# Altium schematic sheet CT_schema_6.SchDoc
size 582 x 363 mm
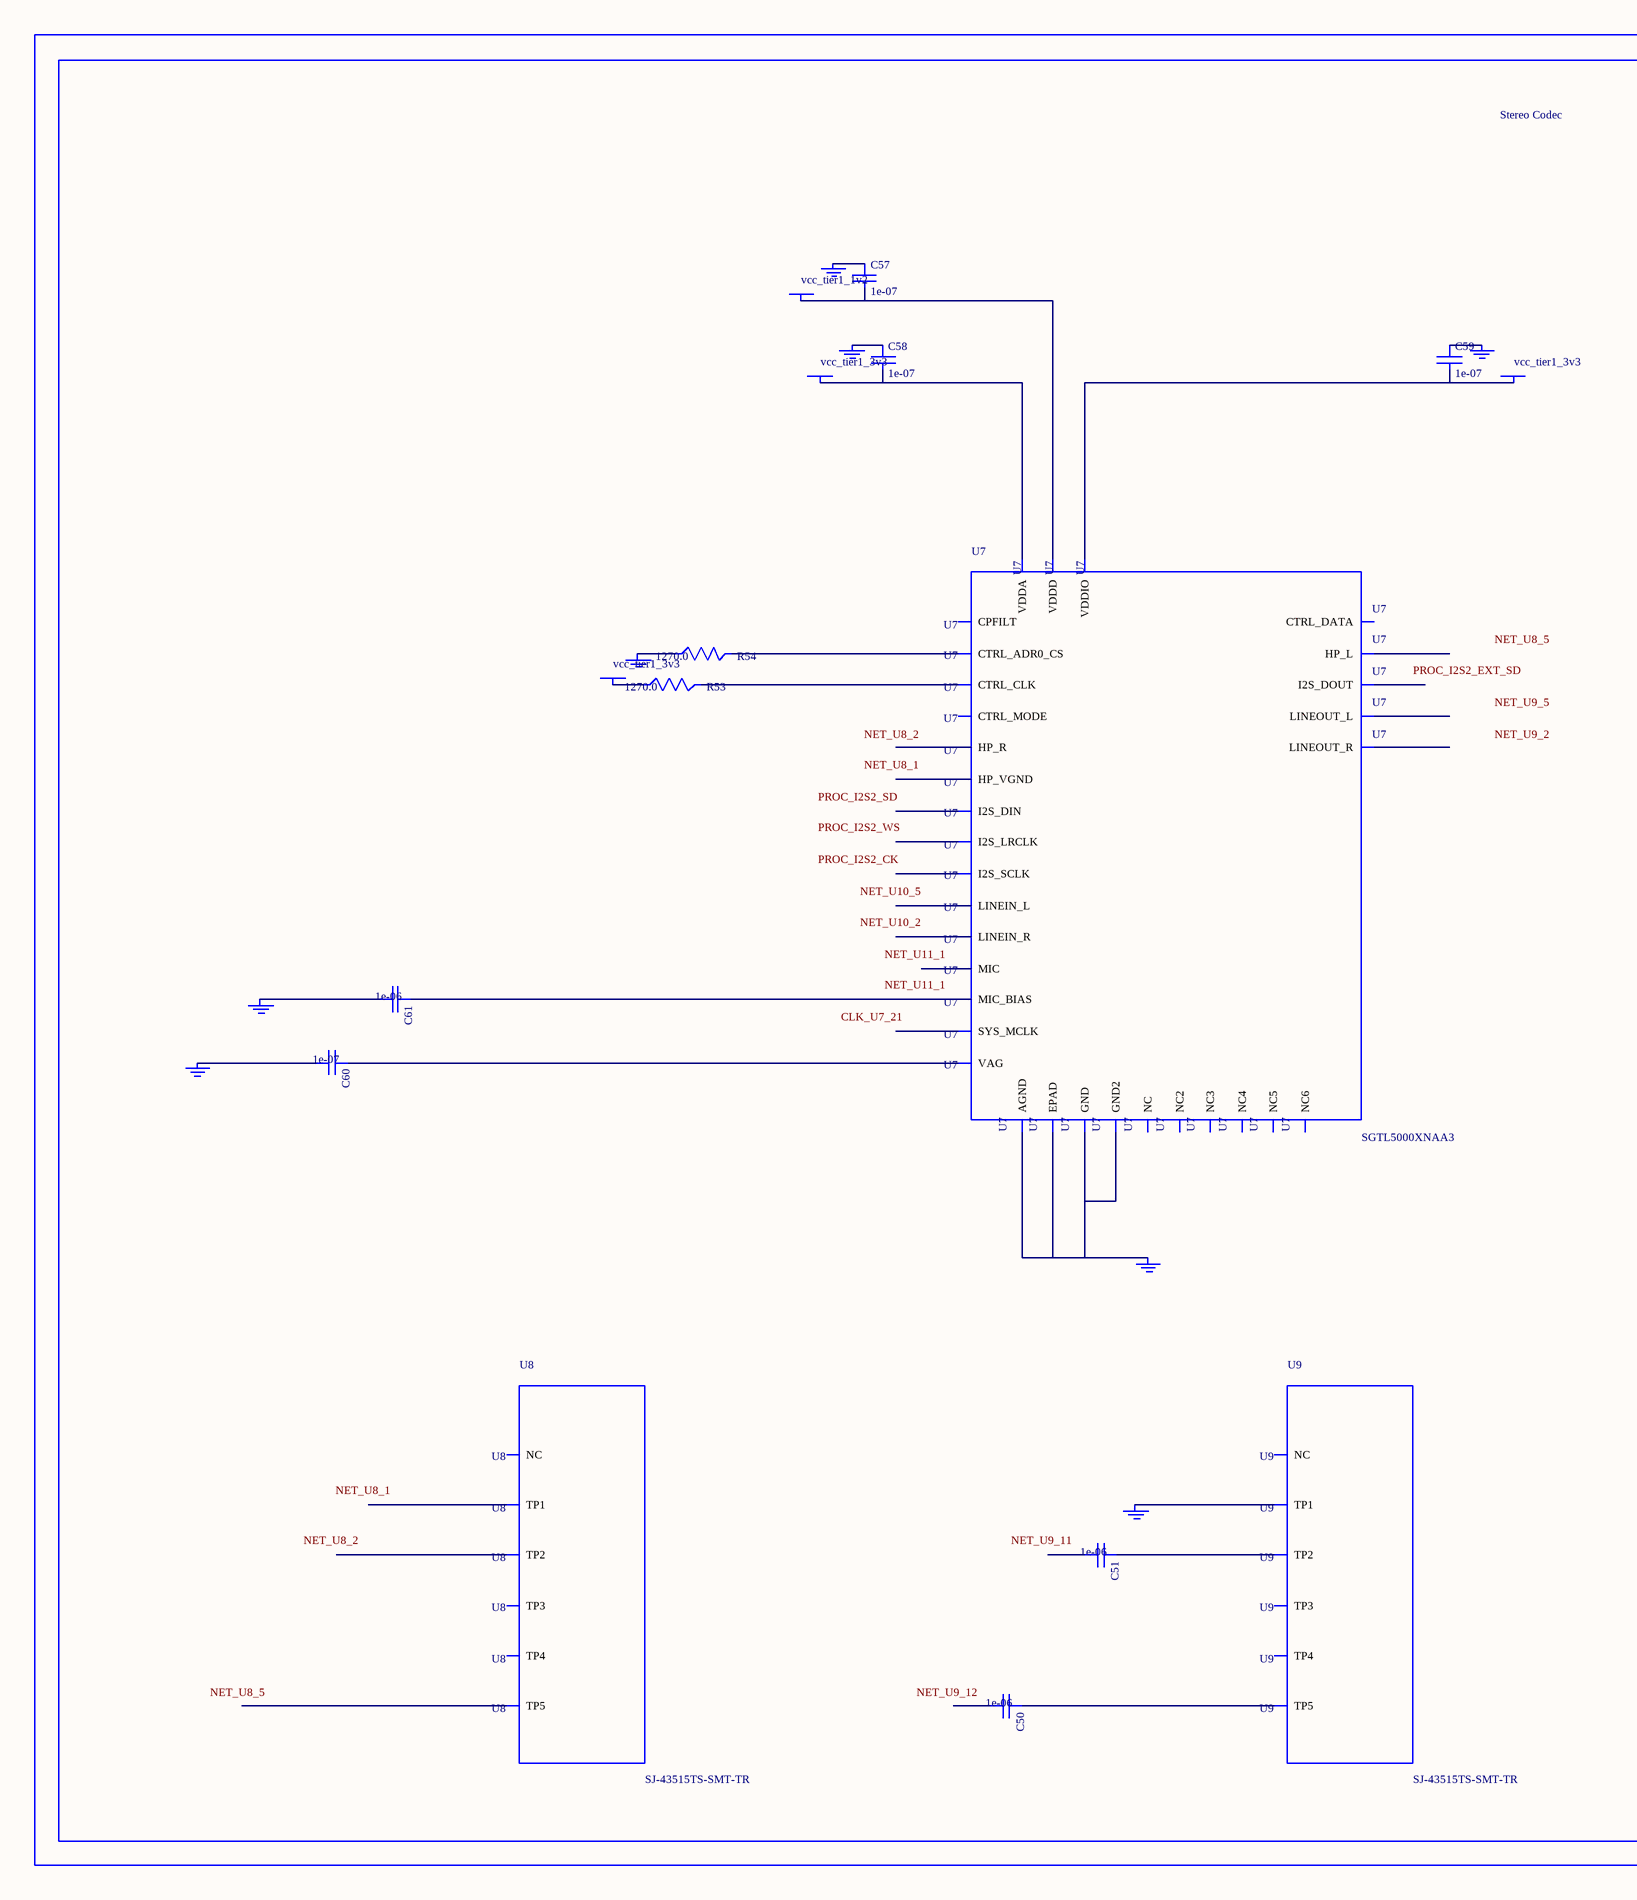
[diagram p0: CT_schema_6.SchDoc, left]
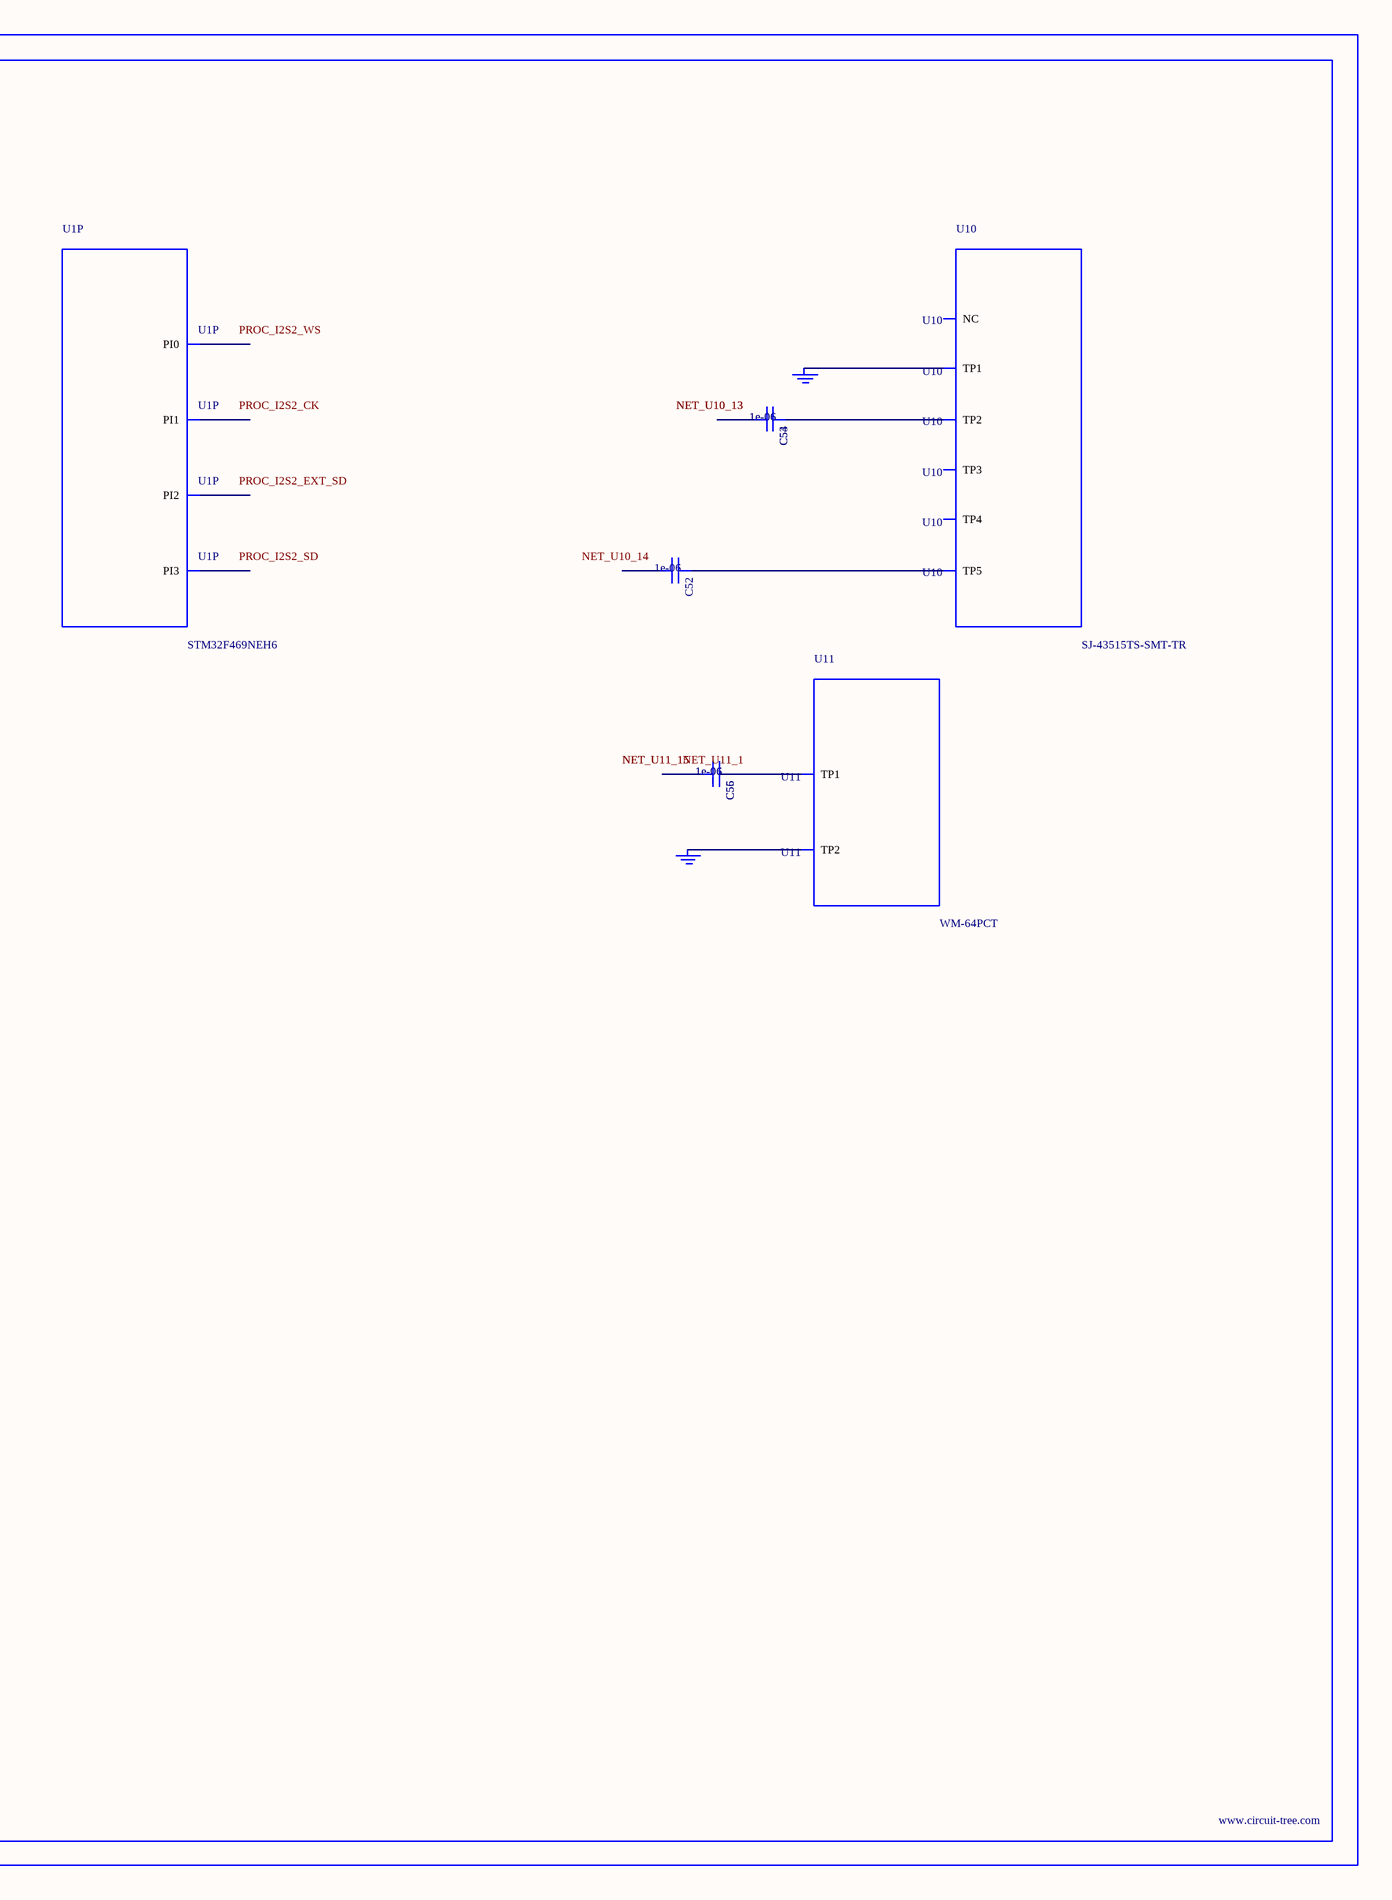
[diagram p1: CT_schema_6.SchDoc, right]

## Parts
BORDER5  (no value)
C50  1e-06  [C0603]
C51  1e-06  [C0603]
C52  1e-06  [C0603]
C53  1e-06  [C0603]
C54  1e-06  [C0603]
C55  1e-06  [C0603]
C56  1e-06  [C0603]
C57  1e-07  [C0402]
C58  1e-07  [C0402]
C59  1e-07  [C0402]
C60  1e-07  [C0402]
C61  1e-06  [C0603]
GND_INSTANCE_5_0  (no value)
GND_INSTANCE_5_1  (no value)
GND_INSTANCE_5_2  (no value)
GND_INSTANCE_5_3  (no value)
GND_INSTANCE_5_4  (no value)
GND_INSTANCE_5_5  (no value)
GND_INSTANCE_5_6  (no value)
GND_INSTANCE_5_7  (no value)
GND_INSTANCE_5_8  (no value)
GND_INSTANCE_5_9  (no value)
GND_INSTANCE_5_10  (no value)
POWER_INSTANCE_5_0  vcc_tier1_3v3
POWER_INSTANCE_5_1  vcc_tier1_3v3
POWER_INSTANCE_5_2  vcc_tier1_3v3
POWER_INSTANCE_5_3  vcc_tier1_1v2
R53  1270.0  [R0603]
R54  1270.0  [R0603]
U1  STM32F469NEH6  [TFBGA216]  (part P of 17)
U7  SGTL5000XNAA3  [QFN-32]
U8  SJ-43515TS-SMT-TR  [SJ-43515TS-SMT-TR]
U9  SJ-43515TS-SMT-TR  [SJ-43515TS-SMT-TR]
U10  SJ-43515TS-SMT-TR  [SJ-43515TS-SMT-TR]
U11  WM-64PCT  [WM-64PC]

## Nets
NetC50_1: C50.1 U9.5(TP5)
NetC51_1: C51.1 U9.2(TP2)
NetC52_1: C52.1 U10.5(TP5)
NetC53_1: C53.1 C54.1 U10.2(TP2)
NetC53_2: C53.2 C54.2
NetC55_1: C55.1 C56.1 U11.1(TP1)
NetC55_2: C55.2 C56.2
NetC57_1: C57.1 GND_INSTANCE_5_5.0(GND)
NetC57_2: C57.2 POWER_INSTANCE_5_3.0(PWR) U7.30(VDDD)
NetC58_1: C58.1 GND_INSTANCE_5_1.0(GND)
NetC58_2: C58.2 POWER_INSTANCE_5_0.0(PWR) U7.5(VDDA)
NetC59_1: C59.1 GND_INSTANCE_5_4.0(GND)
NetC59_2: C59.2 POWER_INSTANCE_5_1.0(PWR) U7.20(VDDIO)
NetC60_1: C60.1 U7.10(VAG)
NetC60_2: C60.2 GND_INSTANCE_5_2.0(GND)
NetC61_1: C61.1 U7.16(MIC_BIAS)
NetC61_2: C61.2 GND_INSTANCE_5_3.0(GND)
NetGND_INSTANCE_5_0_0: GND_INSTANCE_5_0.0(GND) U7.1(GND) U7.3(GND2) U7.7(AGND) U7.EXP(EPAD)
NetGND_INSTANCE_5_6_0: GND_INSTANCE_5_6.0(GND) R54.1
NetGND_INSTANCE_5_7_0: GND_INSTANCE_5_7.0(GND) U9.1(TP1)
NetGND_INSTANCE_5_8_0: GND_INSTANCE_5_8.0(GND) GND_INSTANCE_5_9.0(GND) U10.1(TP1)
NetGND_INSTANCE_5_10_0: GND_INSTANCE_5_10.0(GND) U11.2(TP2)
NetPOWER_INSTANCE_5_2_0: POWER_INSTANCE_5_2.0(PWR) R53.1
NetR53_2: R53.2 U7.29(CTRL_CLK)
NetR54_2: R54.2 U7.31(CTRL_ADR0_CS)

Not connected (* = marked no-connect by the designer): C50 2; C51 2; C52 2; U1 C13(PI3) C14(PI2) D14(PI1) E14(PI0); U7 2(HP_R) 4(HP_VGND) 6(HP_L) 8(NC) 9(NC2) 11(LINEOUT_R) 12(LINEOUT_L) 13(LINEIN_R) 14(LINEIN_L) 15(MIC) 17(NC3) 18(CPFILT) 19(NC4) 21(SYS_MCLK) 22(NC5) 23(I2S_LRCLK) 24(I2S_SCLK) 25(I2S_DOUT) 26(I2S_DIN) 27(CTRL_DATA) 28(NC6) 32(CTRL_MODE); U8 1(TP1) 2(TP2) 3(TP3) 4(TP4) 5(TP5) 6(NC); U9 3(TP3) 4(TP4) 6(NC); U10 3(TP3) 4(TP4) 6(NC)

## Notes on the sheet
- Labels drawn without touching a wire or pin: CLK_U7_21, NET_U8_1, NET_U8_2, NET_U8_5, NET_U9_2, NET_U9_5, NET_U9_11, NET_U9_12, NET_U10_2, NET_U10_5, NET_U10_14, NET_U11_1, PROC_I2S2_CK, PROC_I2S2_EXT_SD, PROC_I2S2_SD, PROC_I2S2_WS

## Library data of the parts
BORDER5 = BORDER_PAGE5
C50-C56 C61 = C0603C105K3RACTU
C57-C60 = C0402C104K3RACTU
GND_INSTANCE_5_0-GND_INSTANCE_5_10 = GND
POWER_INSTANCE_5_0-POWER_INSTANCE_5_3 = PWR
R53 R54 = RC0603FR-071K27L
